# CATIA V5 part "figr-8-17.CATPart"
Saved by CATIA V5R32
Part number: Part1
Bounding box of the stored display mesh (mm): x -55.501 to 55.501, y -84.223 to 84.223, z 0 to 81
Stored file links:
  D:\PROJECTS\Project 2022\CATIA V5 6R 2022\Resources\Part Files\c08_catia_v5_6r2022_prt\figr-8-17.CATPart
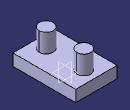
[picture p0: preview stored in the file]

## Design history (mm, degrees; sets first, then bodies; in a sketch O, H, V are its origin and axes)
Body1 (main body)
  Sketch1 on xy-plane, origin (0, 0, 0), H (1, 0, 0), V (0, 1, 0)
    line L1 (-55.501, 84.2232) -> (55.501, 84.2232)
    line L2 (55.501, 84.2232) -> (55.501, -84.2232)
    line L3 (55.501, -84.2232) -> (-55.501, -84.2232)
    line L4 (-55.501, -84.2232) -> (-55.501, 84.2232)
    axis line L5 (55.501, -84.2232) -> (-55.501, 84.2232)
    horizontal: L1 H, L3 H
    vertical: L2 V, L4 V
    midpoint: O L5
  Pad1: profile Sketch1, direction (0, 0, 1), length 31
  Sketch2 on face of Pad1, origin (0, 0, 31), H (1, 0, 0), V (0, 1, 0)
    circle A1 centre (0, -50.4568) radius 18.9426
    point P1 (0, -50.4568)
    coincidence: P1 V
  Pad2: profile Sketch2, direction (0, 0, 1), length 50
  Mirror1: of Pad2, Sketch2, about zx-plane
